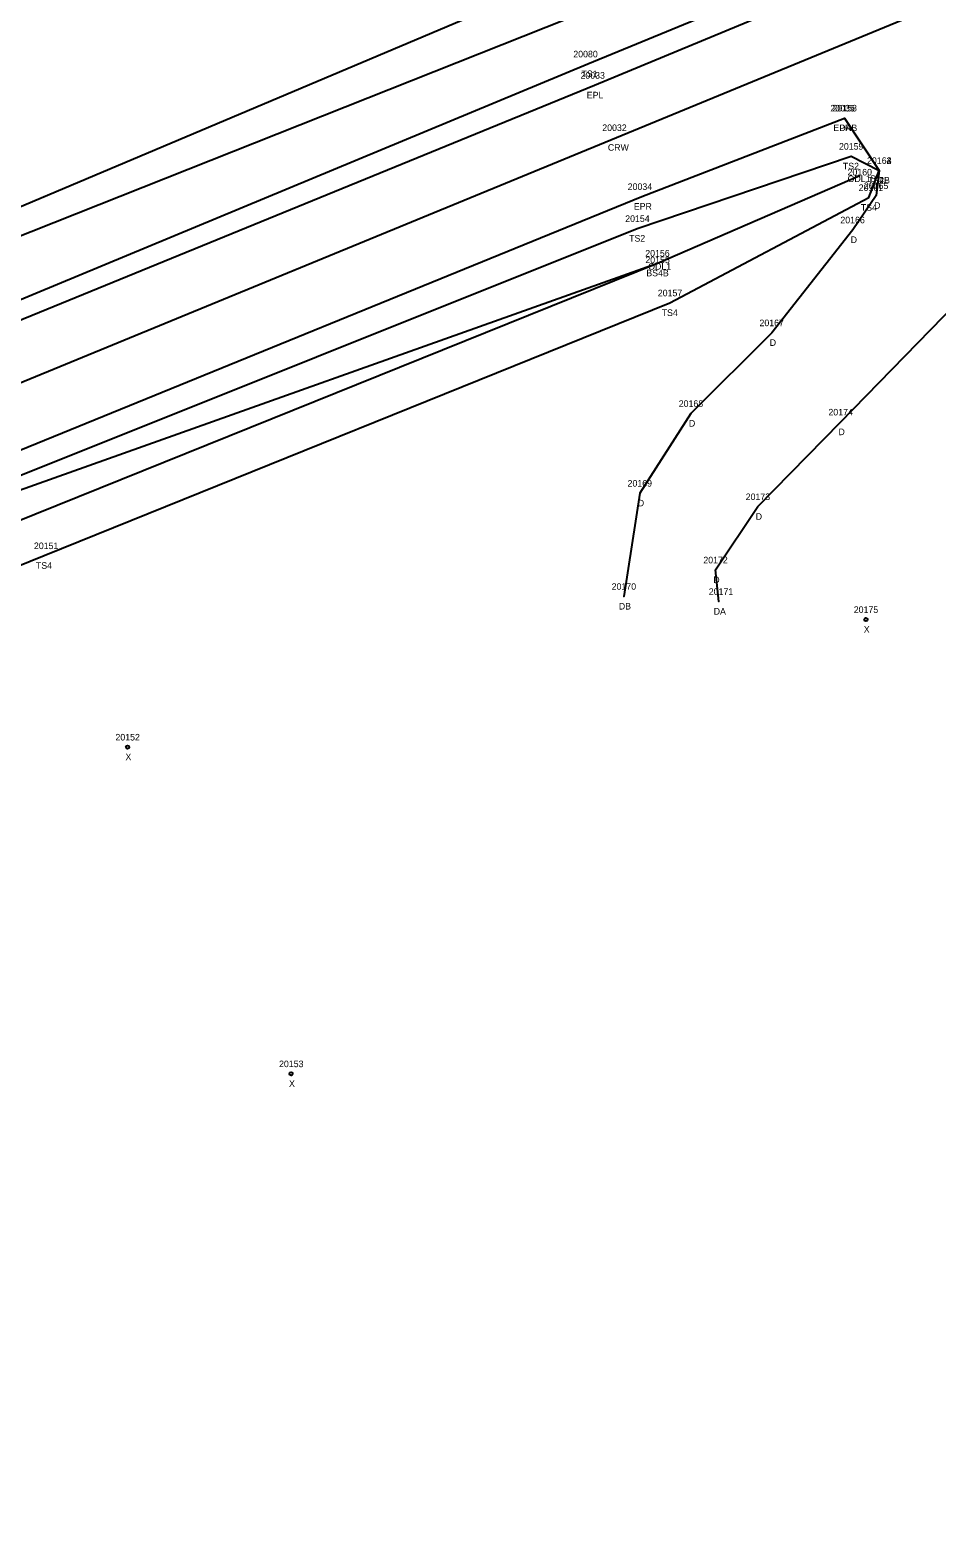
# Model space of a CAD drawing. Extents: x 1966740 to 1969291, y 1117378 to 1118461.
# Drawn here: x 1967184.9 to 1967322.9, y 1117440.6 to 1117670 of the extents above; entities that cross this region are included whole.
import ezdxf

# ---------------------------------------------------------------- set-up
doc = ezdxf.new("R2010")
doc.units = 0
for name, color, linetype in [('RD_DTM_BkLn1', 7, 'Continuous'), ('RD_DTM_BkLn2', 7, 'Continuous'), ('RD_EX_Driveway', 7, 'Continuous'), ('RD_EX_Driveway_txCode', 7, 'Continuous'), ('RD_EX_H2O', 7, 'Continuous'), ('RD_EX_H2O_txCode', 7, 'Continuous'), ('RD_EX_Road', 7, 'Continuous'), ('RD_EX_Road_txCode', 7, 'Continuous'), ('RD_SMD_Locator', 7, 'Continuous'), ('RD_SMD_Misc', 7, 'Continuous')]:
    doc.layers.add(name, color=color, linetype=linetype)

msp = doc.modelspace()

# ---------------------------------------------------------------- linework, layer by layer
at = {"layer": 'RD_DTM_BkLn1'}
msp.add_lwpolyline([(1966772.57, 1117449.88), (1966874.49, 1117489.87), (1966974.64, 1117529.93), (1967075.06, 1117571.68), (1967175.91, 1117613.34), (1967274.11, 1117653.69), (1967325.25, 1117674.8), (1967374.73, 1117695), (1967473.9, 1117733.1), (1967569.8, 1117771.9), (1967665.19, 1117809.79), (1967697.89, 1117822.8)], dxfattribs=at)
at = {"layer": 'RD_DTM_BkLn2'}
for points in [[(1966768.15, 1117461.43), (1966869.41, 1117499.34), (1967070.52, 1117582.35), (1967171.25, 1117624.02), (1967269.74, 1117664.9), (1967320.21, 1117685.71), (1967369.37, 1117708.48), (1967468.51, 1117746.66), (1967564.6, 1117784.47), (1967654.68, 1117828.05), (1967680.1, 1117841.48), (1967687.91, 1117842.93), (1967691.45, 1117838.71), (1967693.03, 1117834.22)], [(1966766.42, 1117472.19), (1966865.47, 1117508.82), (1967066.64, 1117593.45), (1967166.55, 1117636.11), (1967264.62, 1117677.56), (1967315.66, 1117698.57), (1967367.9, 1117716.34), (1967464.92, 1117753.87), (1967560.73, 1117793.63)], [(1967048.76, 1117544.94), (1967049.4, 1117546.86), (1967080.66, 1117559.16), (1967179.58, 1117600.77), (1967277.28, 1117639.86), (1967309.81, 1117650.85), (1967314.11, 1117648.69)], [(1967048.76, 1117544.94), (1967051.21, 1117542.08), (1967082.51, 1117547.84), (1967186.99, 1117590.06), (1967282.24, 1117628.54), (1967312.54, 1117644.56), (1967314.11, 1117648.69)], [(1967057.9, 1117544.76), (1967083.08, 1117552.93), (1967182.44, 1117595.12), (1967280.35, 1117634.58)]]:
    msp.add_lwpolyline(points, dxfattribs=at)
at = {"layer": 'RD_EX_Driveway'}
for points in [[(1967289.71, 1117583.09), (1967289.16, 1117587.89), (1967295.61, 1117597.52), (1967308.21, 1117610.4), (1967325.87, 1117628.48), (1967333.04, 1117643.27), (1967334.06, 1117655.75), (1967333.75, 1117659.51), (1967340.03, 1117669.86)], [(1967308.82, 1117656.67), (1967314.11, 1117648.69), (1967313.63, 1117644.86), (1967310.07, 1117639.65), (1967297.74, 1117623.99), (1967285.44, 1117611.7), (1967277.66, 1117599.57), (1967275.25, 1117583.86)]]:
    msp.add_lwpolyline(points, dxfattribs=at)
at = {"layer": 'RD_EX_H2O'}
for points in [[(1966766.64, 1117466.58), (1966867.24, 1117504.5), (1967068.76, 1117586.41), (1967167.95, 1117632.67), (1967266.82, 1117671.88), (1967316.79, 1117693.47), (1967368.01, 1117713.34), (1967465.67, 1117751.74), (1967560.73, 1117793.63)], [(1967050.24, 1117545.72), (1967081, 1117557.52), (1967180.2, 1117598.94), (1967280.35, 1117634.58), (1967311.17, 1117647.93)]]:
    msp.add_lwpolyline(points, dxfattribs=at)
at = {"layer": 'RD_EX_Road'}
for points in [[(1966769.51, 1117457.48), (1966870.16, 1117497.34), (1966971.19, 1117538.95), (1967071.09, 1117580.24), (1967172.6, 1117621.53), (1967270.79, 1117661.66), (1967321.12, 1117682.57), (1967371.52, 1117702.88), (1967470.26, 1117741.55), (1967566.67, 1117779.5), (1967661.25, 1117817.53), (1967694.4, 1117831.19), (1967697.89, 1117822.8)], [(1966775.75, 1117440.57), (1966876.18, 1117480.39), (1966978.46, 1117522.15), (1967078.26, 1117563.06), (1967180.7, 1117605.06), (1967277.98, 1117644.72), (1967308.82, 1117656.67)]]:
    msp.add_lwpolyline(points, dxfattribs=at)
at = {"layer": 'RD_SMD_Locator'}
for centre, radius in [((1967269.74, 1117664.9), 0.001), ((1967270.79, 1117661.66), 0.001), ((1967308.82, 1117656.67), 0.001), ((1967308.82, 1117656.67), 0.001), ((1967274.11, 1117653.69), 0.001), ((1967309.81, 1117650.85), 0.001), ((1967314.11, 1117648.69), 0.001), ((1967314.11, 1117648.69), 0.001), ((1967314.11, 1117648.69), 0.001), ((1967311.17, 1117647.93), 0.001), ((1967277.98, 1117644.72), 0.001), ((1967312.54, 1117644.56), 0.001), ((1967313.63, 1117644.86), 0.001), ((1967277.28, 1117639.86), 0.001), ((1967310.07, 1117639.65), 0.001), ((1967280.35, 1117634.58), 0.001), ((1967280.35, 1117634.58), 0.001), ((1967282.24, 1117628.54), 0.001), ((1967297.74, 1117623.99), 0.001), ((1967285.44, 1117611.7), 0.001), ((1967308.21, 1117610.4), 0.001), ((1967277.66, 1117599.57), 0.001), ((1967295.61, 1117597.52), 0.001), ((1967186.99, 1117590.06), 0.001), ((1967289.16, 1117587.89), 0.001), ((1967275.25, 1117583.86), 0.001), ((1967289.71, 1117583.09), 0.001), ((1967312.07, 1117580.34), 0.25), ((1967199.69, 1117560.93), 0.25), ((1967224.58, 1117511.21), 0.25)]:
    msp.add_circle(centre, radius, dxfattribs=at)

# ---------------------------------------------------------------- texts
at = {"layer": 'RD_EX_Driveway_txCode'}
for s, p in [('20158', (1967306.99, 1117657.67)), ('DA', (1967308.03, 1117654.67)), ('20164', (1967312.25, 1117649.69)), ('20165', (1967311.77, 1117645.86)), ('D', (1967313.8, 1117646.69)), ('20166', (1967308.19, 1117640.65)), ('D', (1967313.33, 1117642.86)), ('D', (1967309.76, 1117637.65)), ('20167', (1967295.88, 1117624.99)), ('D', (1967297.44, 1117621.99)), ('20168', (1967283.59, 1117612.7)), ('20174', (1967306.37, 1117611.4)), ('D', (1967285.14, 1117609.7)), ('D', (1967307.9, 1117608.4)), ('20169', (1967275.8, 1117600.57)), ('D', (1967277.36, 1117597.57)), ('20173', (1967293.78, 1117598.52)), ('D', (1967295.31, 1117595.52)), ('20172', (1967287.33, 1117588.89)), ('D', (1967288.85, 1117585.89)), ('20170', (1967273.38, 1117584.86)), ('20171', (1967288.16, 1117584.09)), ('DB', (1967274.47, 1117581.86)), ('DA', (1967288.91, 1117581.09))]:
    msp.add_text(s, height=1, dxfattribs=at).set_placement(p)
at = {"layer": 'RD_EX_H2O_txCode'}
for s, p in [('20160', (1967309.28, 1117647.93)), ('ODL1B', (1967309.29, 1117646.93)), ('20155', (1967278.51, 1117634.58)), ('ODL1', (1967278.94, 1117633.58))]:
    msp.add_text(s, height=1, dxfattribs=at).set_placement(p)
at = {"layer": 'RD_EX_Road_txCode'}
for s, p in [('20033', (1967268.63, 1117662.66)), ('EPL', (1967269.59, 1117659.66)), ('20035', (1967306.67, 1117657.67)), ('EPRB', (1967307.12, 1117654.67)), ('20034', (1967275.82, 1117645.72)), ('EPR', (1967276.75, 1117642.72))]:
    msp.add_text(s, height=1, dxfattribs=at).set_placement(p)
at = {"layer": 'RD_SMD_Misc'}
for s, p in [('20080', (1967267.54, 1117665.9)), ('TS1', (1967268.78, 1117662.9)), ('20032', (1967271.95, 1117654.69)), ('CRW', (1967272.8, 1117651.69)), ('20159', (1967307.98, 1117651.85)), ('TS2', (1967308.57, 1117648.85)), ('20162', (1967312.25, 1117649.69)), ('20163', (1967312.25, 1117649.69)), ('20161', (1967310.97, 1117645.56)), ('TS2B', (1967312.39, 1117646.69)), ('TS4B', (1967312.39, 1117646.69)), ('20154', (1967275.44, 1117640.86)), ('TS4', (1967311.3, 1117642.56)), ('TS2', (1967276.03, 1117637.86)), ('20156', (1967278.49, 1117635.58)), ('BS4B', (1967278.65, 1117632.58)), ('20157', (1967280.4, 1117629.54)), ('TS4', (1967280.99, 1117626.54)), ('20151', (1967185.44, 1117591.06)), ('TS4', (1967185.74, 1117588.06)), ('20175', (1967310.23, 1117581.34)), ('X', (1967311.75, 1117578.34)), ('20152', (1967197.85, 1117561.93)), ('X', (1967199.37, 1117558.93)), ('20153', (1967222.75, 1117512.21)), ('X', (1967224.27, 1117509.21))]:
    msp.add_text(s, height=1, dxfattribs=at).set_placement(p)

doc.saveas('drawing.dxf')
